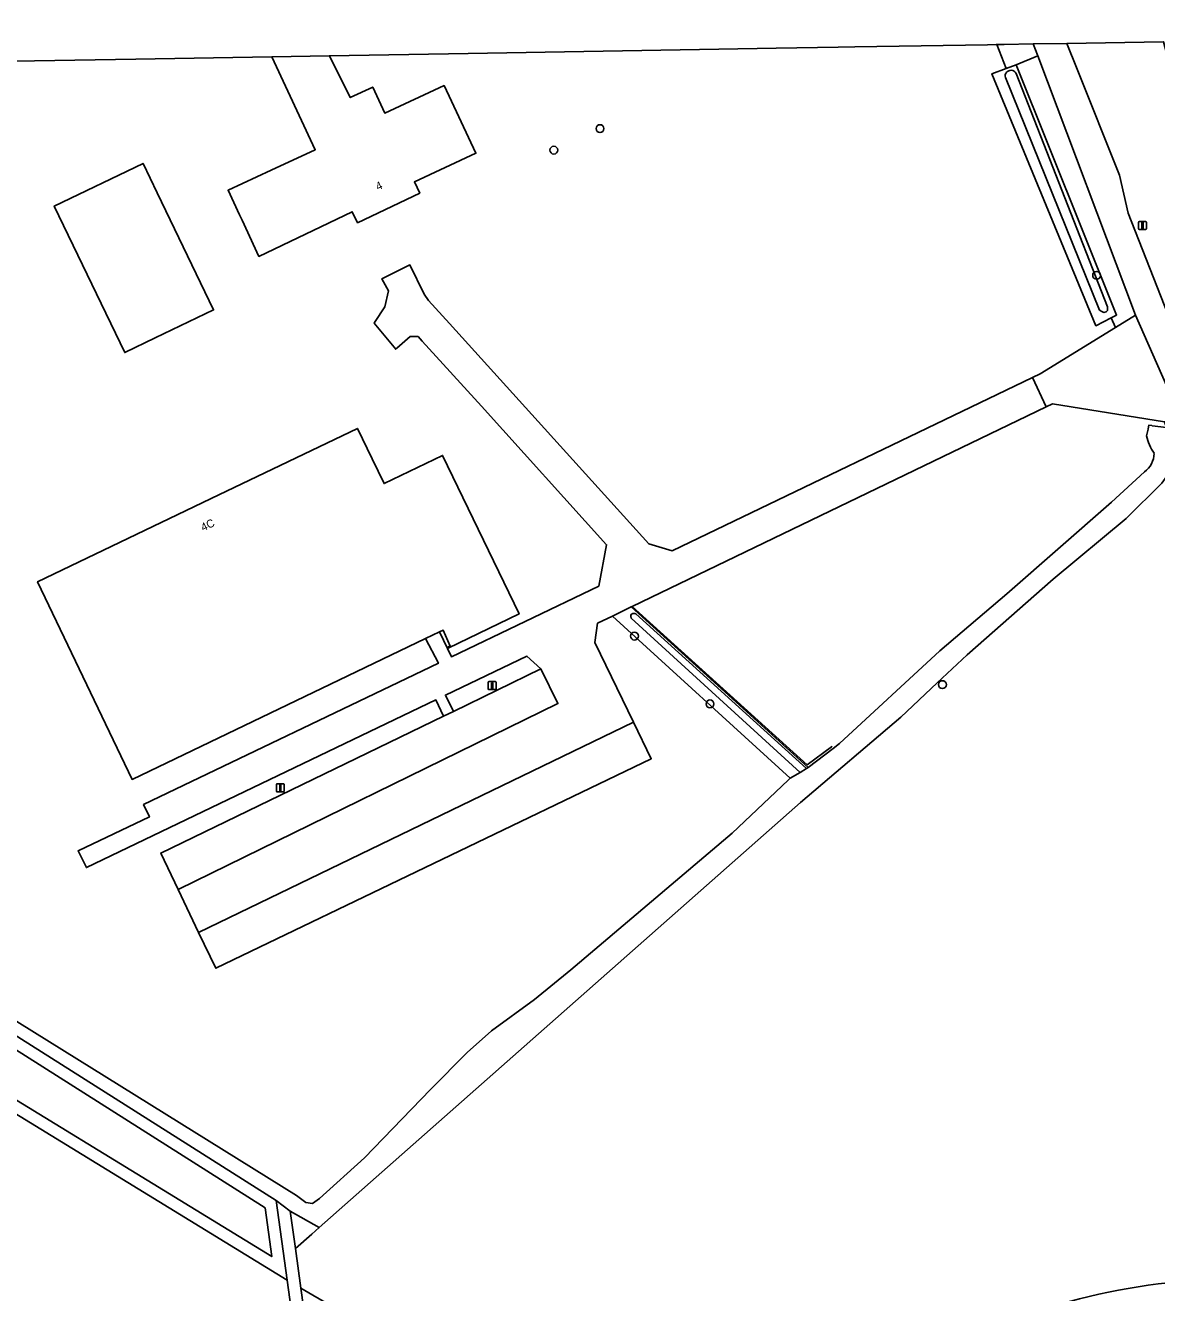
# Model space of a CAD drawing. Extents: x 161385 to 162589, y 388479 to 389756.
# Drawn here: x 162288.4 to 162429.6, y 389597.2 to 389755.5 of the extents above; entities that cross this region are included whole.
import ezdxf

# ---------------------------------------------------------------- set-up
doc = ezdxf.new("R2010")
doc.units = 0
for name, color, linetype in [('IMGEO_Berm_groen', 7, 'Continuous'), ('IMGEO_Boom', 7, 'Continuous'), ('IMGEO_Bouwland', 7, 'Continuous'), ('IMGEO_Erf', 7, 'Continuous'), ('IMGEO_Gemengd_bos', 7, 'Continuous'), ('IMGEO_Groenvoorziening', 7, 'Continuous'), ('IMGEO_Hek', 7, 'Continuous'), ('IMGEO_Lichtmast', 7, 'Continuous'), ('IMGEO_Loofbos', 7, 'Continuous'), ('IMGEO_Oever', 7, 'Continuous'), ('IMGEO_Pand', 7, 'Continuous'), ('IMGEO_Pand_nummerreeks', 7, 'Continuous'), ('IMGEO_Parkeervlak_open', 7, 'Continuous'), ('IMGEO_Rijbaan_lokaal_gesloten', 7, 'Continuous'), ('IMGEO_Rijbaan_lokaal_open', 7, 'Continuous'), ('IMGEO_Waterloop', 7, 'Continuous')]:
    doc.layers.add(name, color=color, linetype=linetype)

msp = doc.modelspace()

# ---------------------------------------------------------------- linework, layer by layer
at = {"layer": 'IMGEO_Berm_groen'}
msp.add_lwpolyline([(162414.82, 389751.67), (162412.08, 389750.54), (162424.63, 389719.27), (162423.97, 389718.93), (162424.48, 389717.71), (162426.99, 389719.26)], close=True, dxfattribs=at)
at = {"layer": 'IMGEO_Boom'}
for centre in [(162360.14, 389742.56), (162354.37, 389739.87), (162422.14, 389724.23), (162364.44, 389679.17), (162402.89, 389673.11), (162373.87, 389670.7)]:
    msp.add_circle(centre, 0.489, dxfattribs=at)
at = {"layer": 'IMGEO_Bouwland'}
msp.add_lwpolyline([(162496.19, 389612.91), (162481.08, 389632.53), (162456.22, 389661.77), (162455.16, 389662.82), (162449.46, 389669.13), (162445.05, 389674.92), (162440.48, 389682.07), (162436.57, 389689.6), (162431.13, 389699.42), (162430.29, 389698.26), (162425.82, 389693.87), (162416.7, 389686.29), (162405.96, 389676.81), (162402.25, 389673.34), (162397.7, 389669.06), (162385.15, 389658.37), (162325.08, 389605.29), (162324.14, 389604.46), (162322.11, 389602.67), (162322.8, 389597.7), (162339.42, 389588), (162346.95, 389583.61), (162347.95, 389566.2), (162352.65, 389567.29)], dxfattribs=at)
msp.add_arc((162439.59, 389520.52), 78.34, 88.8894, 118.2652, dxfattribs=at)
at = {"layer": 'IMGEO_Erf'}
for points in [[(162444.07, 389753.64), (162500, 389754.58), (162552.12, 389755.46), (162552.12, 389755.46), (162552.12, 389755.46), (162534.43, 389750), (162528.09, 389748.05), (162500, 389739.97), (162468.6, 389731.52), (162459.77, 389728.7), (162443.19, 389723.89), (162435.78, 389721.2), (162434.02, 389720.56), (162431.05, 389719.38), (162426.09, 389732), (162425, 389736.75), (162419.72, 389750), (162418.44, 389753.21), (162430.5, 389753.41), (162431.25, 389750.55)], [(162304.58, 389716.41), (162300.79, 389714.59), (162291.99, 389732.89), (162303.08, 389738.22), (162304.85, 389734.54), (162311.88, 389719.92)], [(162352.76, 389675.1), (162351.01, 389676.68), (162340.84, 389671.8), (162341.83, 389669.75)], [(162321.07, 389598.73), (162271.67, 389628.98), (162262.97, 389614.25), (162261.33, 389609.47), (162261.33, 389604.96), (162261.89, 389601.4), (162269.93, 389569.01), (162278.94, 389531.43), (162280.27, 389528.23), (162280.47, 389527.21), (162280.78, 389526.82), (162281.86, 389525.47), (162301, 389533.64), (162324.11, 389543.91), (162328.57, 389545.88), (162328, 389548.66)]]:
    msp.add_lwpolyline(points, close=True, dxfattribs=at)
for points in [[(162409.7, 389753.06), (162409.61, 389753.06), (162408.53, 389753.04), (162391.96, 389752.76), (162389.86, 389752.73), (162382.12, 389752.6), (162374.99, 389752.48), (162343.67, 389751.95), (162326.35, 389751.66), (162328.96, 389746.44), (162331.76, 389747.74), (162333.27, 389744.49), (162340.67, 389747.93), (162344.64, 389739.48), (162336.96, 389735.91), (162337.64, 389734.5), (162329.87, 389730.79), (162329.2, 389732.17), (162317.54, 389726.6), (162315.44, 389731.14), (162315.13, 389731.8), (162313.71, 389734.86), (162319.06, 389737.35), (162324.58, 389739.91), (162319.18, 389751.54), (162302.17, 389751.25), (162266.69, 389750.65)], [(162283.86, 389633.15), (162322.24, 389609.3), (162323.41, 389608.41), (162324.23, 389608.31), (162325.1, 389608.92), (162330.73, 389613.98), (162338.96, 389622.53), (162343.56, 389627.15), (162346.58, 389629.85), (162351.96, 389633.79), (162356.51, 389637.5), (162376.62, 389654.57), (162383.61, 389661.17), (162383.86, 389661.41), (162361.69, 389681.67), (162359.84, 389680.78), (162359.5, 389678.39), (162364.33, 389668.41), (162366.54, 389663.85), (162312.16, 389637.67), (162310.02, 389642.15), (162307.45, 389647.53), (162305.29, 389652.06), (162340.59, 389669.18), (162339.65, 389671.19), (162296.01, 389650.25), (162294.98, 389652.36), (162303.87, 389656.59), (162303.14, 389658.13), (162339.96, 389675.77), (162338.36, 389678.88), (162301.72, 389661.27), (162289.91, 389685.95), (162312.54, 389696.81), (162329.85, 389705.11), (162331.68, 389701.31), (162333.17, 389698.21), (162340.48, 389701.73), (162350.04, 389681.93), (162341.16, 389677.66), (162341.11, 389677.8), (162341.43, 389677.93), (162340.54, 389679.92), (162340.08, 389679.71), (162341.58, 389676.58), (162359.97, 389685.41), (162360.96, 389690.57), (162345.32, 389707.88), (162337.92, 389716.02), (162337.42, 389716.58), (162336.42, 389716.6), (162334.78, 389715.13), (162334.63, 389715), (162331.93, 389718.24), (162332, 389718.35), (162333.28, 389720.28), (162333.73, 389722.28), (162332.91, 389723.81), (162336.4, 389725.53), (162338.18, 389721.9), (162338.74, 389721.1), (162341.35, 389718.21), (162366.23, 389690.69), (162369.14, 389689.82), (162414.14, 389711.47), (162415.11, 389711.94), (162424.48, 389717.71), (162423.97, 389718.93), (162422.05, 389717.94), (162409.08, 389749.41), (162410.86, 389750.08), (162409.7, 389753.06)], [(162428.38, 389704.2), (162428.56, 389705.01), (162428.62, 389705.29), (162428.66, 389705.5), (162429.02, 389705.46), (162429.08, 389705.45), (162430.85, 389705.23), (162430.63, 389705.94), (162416.62, 389708.17), (162415.83, 389707.79), (162364.15, 389682.86), (162364.04, 389682.81), (162386.14, 389662.75), (162389.24, 389665.14), (162390.05, 389665.76), (162402.57, 389677.34), (162410.94, 389684.45)], [(162410.94, 389684.45), (162424.01, 389695.91), (162428.12, 389699.68)]]:
    msp.add_lwpolyline(points, dxfattribs=at)
for centre, radius, start, end in [((162434.41, 389705.48), 6.16, 191.993, 214.4105), ((162426.35, 389702.07), 2.98, 306.463, 358.5648)]:
    msp.add_arc(centre, radius, start, end, dxfattribs=at)
at = {"layer": 'IMGEO_Gemengd_bos'}
for points in [[(162319.7, 389608.65), (162263.58, 389644.22), (162246.6, 389655.44), (162236.3, 389662.76), (162234.97, 389659.31), (162235.38, 389655.73), (162236.05, 389652.32), (162237.74, 389648.7), (162240.27, 389645.31), (162242.31, 389641.95), (162244.42, 389636.24), (162246.5, 389631.2), (162247.78, 389627.23), (162249.36, 389623.36), (162252.34, 389618.7), (162254.13, 389614.5), (162256.25, 389611.92), (162257.29, 389610.26), (162261.33, 389609.47), (162262.97, 389614.25), (162271.67, 389628.98), (162321.07, 389598.73)], [(162319.15, 389601.67), (162271.15, 389631.05), (162261.6, 389614.88), (162260.33, 389611.2), (162258.21, 389611.61), (162257.47, 389612.8), (162255.42, 389615.28), (162253.68, 389619.4), (162250.7, 389624.05), (162249.19, 389627.75), (162247.91, 389631.72), (162245.81, 389636.79), (162243.67, 389642.6), (162241.51, 389646.15), (162239.04, 389649.48), (162237.49, 389652.79), (162236.86, 389655.96), (162236.29, 389660.93), (162245.75, 389654.2), (162262.77, 389642.96), (162318.31, 389607.75)]]:
    msp.add_lwpolyline(points, close=True, dxfattribs=at)
at = {"layer": 'IMGEO_Groenvoorziening'}
msp.add_lwpolyline([(162414.24, 389753.14), (162410.62, 389753.08), (162409.7, 389753.06), (162410.86, 389750.08), (162412.08, 389750.54), (162414.82, 389751.67)], close=True, dxfattribs=at)
at = {"layer": 'IMGEO_Hek'}
for points in [[(162415.83, 389707.79), (162414.14, 389711.47)], [(162389.12, 389665.4), (162389.04, 389665.33), (162386.02, 389663.1), (162364.15, 389682.86)]]:
    msp.add_lwpolyline(points, dxfattribs=at)
at = {"layer": 'IMGEO_Lichtmast'}
for p, q in [((162427.38, 389730.05), (162427.38, 389730.84)), ((162427.38, 389730.84), (162427.38, 389730.05)), ((162427.48, 389730.94), (162428.27, 389730.94)), ((162428.27, 389730.94), (162427.48, 389730.94)), ((162428.37, 389730.84), (162428.37, 389730.05)), ((162428.37, 389730.05), (162428.37, 389730.84)), ((162428.27, 389729.95), (162427.48, 389729.95)), ((162427.48, 389729.95), (162428.27, 389729.95)), ((162346.18, 389672.58), (162346.18, 389673.38)), ((162346.18, 389673.38), (162346.18, 389672.58)), ((162346.28, 389673.48), (162347.07, 389673.48)), ((162347.07, 389673.48), (162346.28, 389673.48)), ((162347.17, 389673.38), (162347.17, 389672.58)), ((162347.17, 389672.58), (162347.17, 389673.38)), ((162347.07, 389672.48), (162346.28, 389672.48)), ((162346.28, 389672.48), (162347.07, 389672.48)), ((162319.83, 389660.72), (162320.62, 389660.72)), ((162320.62, 389660.72), (162319.83, 389660.72)), ((162319.73, 389659.82), (162319.73, 389660.62)), ((162319.73, 389660.62), (162319.73, 389659.82)), ((162320.62, 389659.72), (162319.83, 389659.72)), ((162319.83, 389659.72), (162320.62, 389659.72)), ((162320.72, 389660.62), (162320.72, 389659.82)), ((162320.72, 389659.82), (162320.72, 389660.62))]:
    msp.add_line(p, q, dxfattribs=at)
for points in [[(162427.8, 389730.82), (162427.95, 389730.82), (162427.95, 389730.07), (162427.8, 389730.07), (162427.8, 389730.82)], [(162346.6, 389673.35), (162346.75, 389673.35), (162346.75, 389672.6), (162346.6, 389672.6), (162346.6, 389673.35)], [(162320.15, 389660.59), (162320.3, 389660.59), (162320.3, 389659.84), (162320.15, 389659.84), (162320.15, 389660.59)]]:
    msp.add_lwpolyline(points, dxfattribs=at)
for centre, start, end in [((162427.48, 389730.84), 90, 180), ((162427.48, 389730.84), 90, 180), ((162428.27, 389730.84), 0, 90), ((162428.27, 389730.84), 360, 90), ((162427.48, 389730.05), 180, 270), ((162427.48, 389730.05), 180, 270), ((162428.27, 389730.05), 270, 0), ((162428.27, 389730.05), 270, 0), ((162346.28, 389673.38), 90, 180), ((162346.28, 389673.38), 90, 180), ((162347.07, 389673.38), 0, 90), ((162347.07, 389673.38), 360, 90), ((162346.28, 389672.58), 180, 270), ((162346.28, 389672.58), 180, 270), ((162347.07, 389672.58), 270, 0), ((162347.07, 389672.58), 270, 0), ((162319.83, 389660.62), 90, 180), ((162319.83, 389660.62), 90, 180), ((162320.62, 389660.62), 0, 90), ((162320.62, 389660.62), 360, 90), ((162319.83, 389659.82), 180, 270), ((162319.83, 389659.82), 180, 270), ((162320.62, 389659.82), 270, 0), ((162320.62, 389659.82), 270, 0)]:
    msp.add_arc(centre, 0.1, start, end, dxfattribs=at)
at = {"layer": 'IMGEO_Loofbos'}
for points in [[(162262.77, 389642.96), (162245.75, 389654.2), (162236.29, 389660.93), (162236.86, 389655.96), (162237.49, 389652.79), (162239.04, 389649.48), (162241.51, 389646.15), (162243.67, 389642.6), (162245.81, 389636.79), (162247.91, 389631.72), (162249.19, 389627.75), (162250.7, 389624.05), (162253.68, 389619.4), (162255.42, 389615.28), (162257.47, 389612.8), (162258.21, 389611.61), (162260.33, 389611.2), (162261.6, 389614.88), (162271.15, 389631.05), (162319.15, 389601.67), (162318.31, 389607.75)], [(162325.08, 389605.29), (162321.46, 389607.34), (162322.11, 389602.67), (162324.14, 389604.46)], [(162346.95, 389583.61), (162339.42, 389588), (162322.8, 389597.7), (162325.57, 389577.86), (162328.45, 389559.73), (162334.51, 389562.12), (162338.45, 389563.72), (162344.6, 389565.42), (162347.95, 389566.2)]]:
    msp.add_lwpolyline(points, close=True, dxfattribs=at)
at = {"layer": 'IMGEO_Oever'}
msp.add_lwpolyline([(162412.08, 389750.54), (162410.86, 389750.08), (162409.08, 389749.41), (162422.05, 389717.94), (162423.97, 389718.93), (162424.63, 389719.27)], close=True, dxfattribs=at)
for points in [[(162412.08, 389749.46), (162423.52, 389720.29), (162423.51, 389719.85), (162423.33, 389719.66), (162423.05, 389719.61), (162422.78, 389719.71), (162422.52, 389719.9), (162410.76, 389748.96)], [(162364.47, 389681.99), (162364.63, 389681.93), (162385.9, 389662.62), (162386.14, 389662.75), (162364.04, 389682.81), (162361.69, 389681.67), (162383.86, 389661.41), (162385.11, 389662.15), (162364.02, 389681.42)], [(162364.02, 389681.42), (162363.97, 389681.61)]]:
    msp.add_lwpolyline(points, dxfattribs=at)
for centre, radius, start, end in [((162411.39, 389749.17), 0.664, 138.6021, 198.6767), ((162411.56, 389748.81), 1.05, 94.561, 129.7157), ((162411.51, 389749.24), 0.607, 20.7507, 93.3286), ((162364.38, 389681.64), 0.407, 139.4323, 183.4601), ((162364.35, 389681.59), 0.422, 73.9719, 131.7859)]:
    msp.add_arc(centre, radius, start, end, dxfattribs=at)
at = {"layer": 'IMGEO_Pand'}
for points in [[(162319.18, 389751.54), (162324.58, 389739.91), (162319.06, 389737.35), (162313.71, 389734.86), (162315.13, 389731.8), (162315.44, 389731.14), (162317.54, 389726.6), (162329.2, 389732.17), (162329.87, 389730.79), (162337.64, 389734.5), (162336.96, 389735.91), (162344.64, 389739.48), (162340.67, 389747.93), (162333.27, 389744.49), (162331.76, 389747.74), (162328.96, 389746.44), (162326.35, 389751.66)], [(162304.85, 389734.54), (162303.08, 389738.22), (162291.99, 389732.89), (162300.79, 389714.59), (162304.58, 389716.41), (162311.88, 389719.92)], [(162338.36, 389678.88), (162340.08, 389679.71), (162340.54, 389679.92), (162341.43, 389677.93), (162341.11, 389677.8), (162341.16, 389677.66), (162350.04, 389681.93), (162340.48, 389701.73), (162333.17, 389698.21), (162331.68, 389701.31), (162329.85, 389705.11), (162312.54, 389696.81), (162289.91, 389685.95), (162301.72, 389661.27)]]:
    msp.add_lwpolyline(points, close=True, dxfattribs=at)
at = {"layer": 'IMGEO_Parkeervlak_open'}
for points in [[(162352.76, 389675.1), (162341.83, 389669.75), (162340.59, 389669.18), (162305.29, 389652.06), (162307.45, 389647.53), (162354.89, 389670.75)], [(162366.54, 389663.85), (162364.33, 389668.41), (162310.02, 389642.15), (162312.16, 389637.67)]]:
    msp.add_lwpolyline(points, close=True, dxfattribs=at)
at = {"layer": 'IMGEO_Rijbaan_lokaal_gesloten'}
for points in [[(162440.87, 389697.49), (162431.13, 389719.17), (162431.05, 389719.38), (162426.09, 389732), (162425, 389736.75), (162419.72, 389750), (162418.44, 389753.21), (162414.27, 389753.14), (162414.24, 389753.14)], [(162414.24, 389753.14), (162414.82, 389751.67), (162426.99, 389719.26), (162433.05, 389705.55), (162437.34, 389696.04)]]:
    msp.add_lwpolyline(points, dxfattribs=at)
at = {"layer": 'IMGEO_Rijbaan_lokaal_open'}
for points in [[(162339.65, 389671.19), (162340.59, 389669.18), (162341.83, 389669.75), (162340.84, 389671.8), (162351.01, 389676.68), (162352.76, 389675.1), (162354.89, 389670.75), (162307.45, 389647.53), (162310.02, 389642.15), (162364.33, 389668.41), (162359.5, 389678.39), (162359.84, 389680.78), (162361.69, 389681.67), (162364.04, 389682.81), (162364.15, 389682.86), (162415.83, 389707.79), (162414.14, 389711.47), (162369.14, 389689.82), (162366.23, 389690.69), (162341.35, 389718.21), (162338.74, 389721.1), (162338.18, 389721.9), (162336.4, 389725.53), (162332.91, 389723.81), (162333.73, 389722.28), (162333.28, 389720.28), (162332, 389718.35), (162331.93, 389718.24), (162334.63, 389715), (162334.78, 389715.13), (162336.42, 389716.6), (162337.42, 389716.58), (162337.92, 389716.02), (162345.32, 389707.88), (162360.96, 389690.57), (162359.97, 389685.41), (162341.58, 389676.58), (162340.08, 389679.71), (162338.36, 389678.88), (162339.96, 389675.77), (162303.14, 389658.13), (162303.87, 389656.59), (162294.98, 389652.36), (162296.01, 389650.25)], [(162426.99, 389719.26), (162424.48, 389717.71), (162415.11, 389711.94), (162414.14, 389711.47), (162415.83, 389707.79), (162416.62, 389708.17), (162430.63, 389705.94), (162433.05, 389705.55)]]:
    msp.add_lwpolyline(points, close=True, dxfattribs=at)
at = {"layer": 'IMGEO_Waterloop'}
for points in [[(162410.76, 389748.96), (162422.52, 389719.9), (162422.78, 389719.71), (162423.05, 389719.61), (162423.33, 389719.66), (162423.51, 389719.85), (162423.52, 389720.29), (162412.08, 389749.46)], [(162431.84, 389703.29), (162431.75, 389703.46), (162430.85, 389705.23), (162429.08, 389705.45), (162429.02, 389705.46), (162428.66, 389705.5), (162428.62, 389705.29), (162428.56, 389705.01), (162428.38, 389704.2)], [(162416.7, 389686.29), (162425.82, 389693.87), (162430.29, 389698.26), (162431.13, 389699.42), (162432.1, 389700.75)], [(162428.12, 389699.68), (162424.01, 389695.91), (162410.94, 389684.45), (162402.57, 389677.34), (162390.05, 389665.76), (162389.24, 389665.14), (162386.14, 389662.75), (162385.9, 389662.62), (162385.11, 389662.15), (162383.86, 389661.41), (162383.61, 389661.17), (162376.62, 389654.57), (162356.51, 389637.5), (162351.96, 389633.79), (162346.58, 389629.85), (162343.56, 389627.15), (162338.96, 389622.53), (162330.73, 389613.98), (162325.1, 389608.92), (162324.23, 389608.31), (162323.41, 389608.41), (162322.24, 389609.3), (162283.86, 389633.15)], [(162234.13, 389666.2), (162233.38, 389666.18), (162233.03, 389666.02), (162232.93, 389665.5), (162233.54, 389664.84), (162233.97, 389664.42), (162236.3, 389662.76), (162246.6, 389655.44), (162263.58, 389644.22), (162319.7, 389608.65), (162321.46, 389607.34), (162325.08, 389605.29), (162385.15, 389658.37), (162397.7, 389669.06), (162402.25, 389673.34), (162405.96, 389676.81), (162416.7, 389686.29)], [(162363.97, 389681.61), (162364.02, 389681.42), (162385.11, 389662.15), (162385.9, 389662.62), (162364.63, 389681.93)], [(162364.63, 389681.93), (162364.47, 389681.99)], [(162325.57, 389577.86), (162322.8, 389597.7), (162322.11, 389602.67), (162321.46, 389607.34), (162319.7, 389608.65), (162321.07, 389598.73), (162328, 389548.66), (162328.57, 389545.88), (162328.72, 389545.2), (162328.81, 389544.73), (162330.75, 389545.23), (162330.61, 389546.16), (162330.58, 389546.32), (162328.83, 389557.31), (162335.16, 389559.85), (162339.1, 389561.44), (162345.25, 389563.14), (162348.13, 389563.77), (162356.06, 389565.5), (162365.1, 389568.64)]]:
    msp.add_lwpolyline(points, dxfattribs=at)
for centre, radius, start, end in [((162411.39, 389749.17), 0.664, 138.6021, 198.6767), ((162411.56, 389748.81), 1.05, 94.561, 129.7157), ((162411.51, 389749.24), 0.607, 20.7507, 93.3286), ((162434.41, 389705.48), 6.16, 191.993, 214.4105), ((162426.35, 389702.07), 2.98, 306.463, 358.5648), ((162364.38, 389681.64), 0.407, 139.4323, 183.4601), ((162364.35, 389681.59), 0.422, 73.9719, 131.7859), ((162439.59, 389520.52), 78.34, 88.8894, 118.2652)]:
    msp.add_arc(centre, radius, start, end, dxfattribs=at)

# ---------------------------------------------------------------- texts
at = {"layer": 'IMGEO_Pand_nummerreeks'}
for s, rotation, p in [('4', 25.5477, (162332.42, 389734.8)), ('4C', 25.6384, (162310.59, 389692.23))]:
    msp.add_text(s, height=1, rotation=rotation, dxfattribs=at).set_placement(p)

doc.saveas('drawing.dxf')
